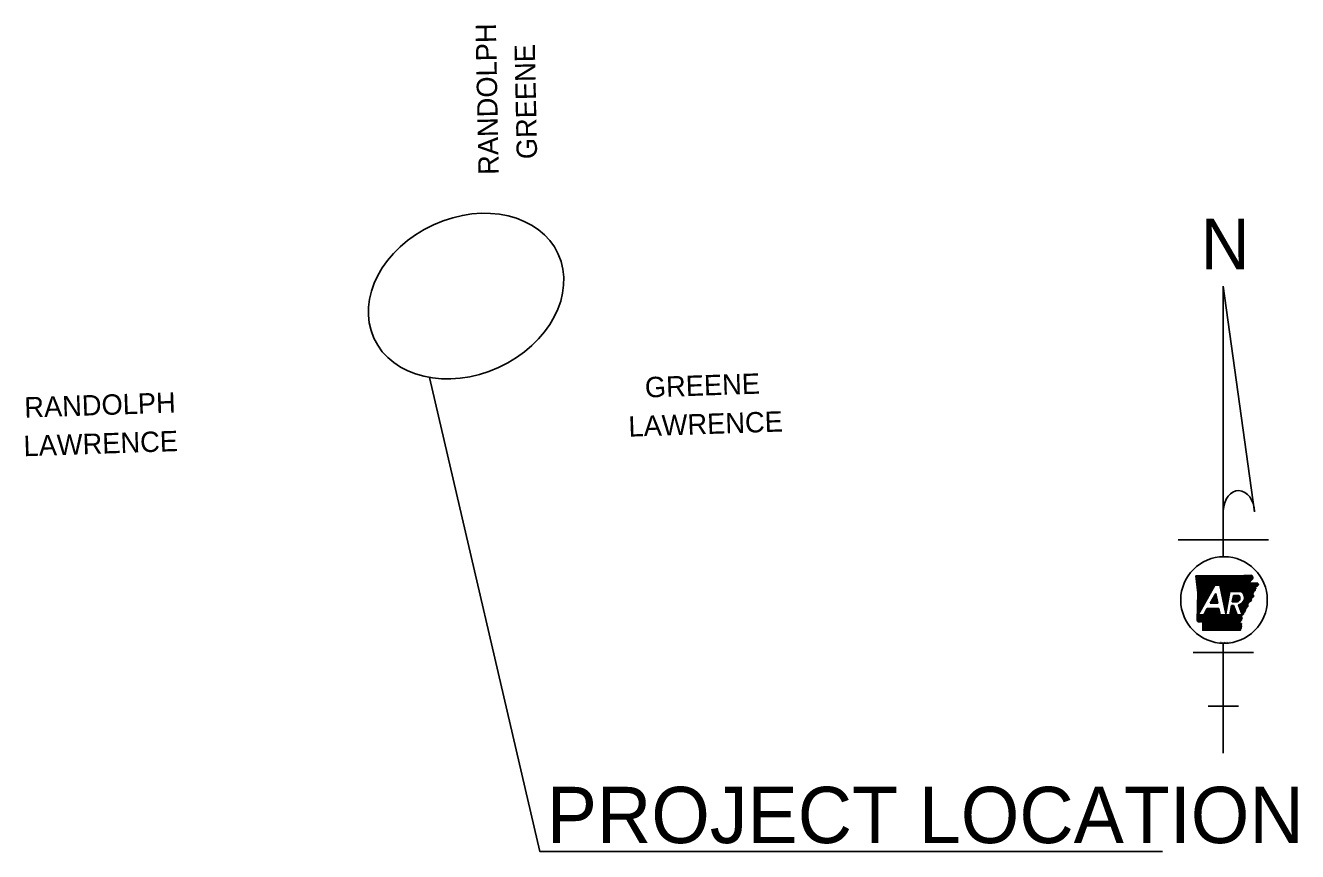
# Model space of a CAD drawing. Extents: x 166 to 3406, y 71 to 2074.
# Drawn here: x 345 to 1136, y 1409 to 1923 of the extents above; entities that cross this region are included whole.
import ezdxf

# ---------------------------------------------------------------- set-up
doc = ezdxf.new("R2010")
doc.units = 0
for name, color, linetype in [('2', 7, 'Continuous'), ('Default', 7, 'Continuous'), ('Level 30', 7, 'Continuous'), ('Level 6', 7, 'Continuous')]:
    doc.layers.add(name, color=color, linetype=linetype)

msp = doc.modelspace()

# ---------------------------------------------------------------- linework, layer by layer
at = {"layer": 'Default'}
msp.add_lwpolyline([(595.91, 1703.74), (664.57, 1409), (1051.65, 1409.03)], dxfattribs=at)
msp.add_ellipse((618.65, 1754.3), major_axis=(-57.31, -26.15), ratio=0.773836, dxfattribs=at)
at = {"layer": 'Level 6'}
for p, q in [((1089.53, 1760.46), (1108.93, 1620.22)), ((1089.53, 1592.29), (1089.53, 1760.46)), ((1061.44, 1602.69), (1117.61, 1602.69)), ((1072.49, 1580.24), (1072.72, 1580.47)), ((1072.57, 1579.58), (1073.47, 1580.47)), ((1072.66, 1578.92), (1074.21, 1580.47)), ((1072.74, 1578.26), (1074.95, 1580.47)), ((1072.82, 1577.6), (1075.7, 1580.47)), ((1072.9, 1576.94), (1076.44, 1580.47)), ((1072.99, 1576.28), (1077.18, 1580.47)), ((1073.07, 1575.62), (1077.92, 1580.47)), ((1073.15, 1574.95), (1078.67, 1580.47)), ((1073.23, 1574.29), (1079.41, 1580.47)), ((1073.32, 1573.63), (1080.15, 1580.47)), ((1073.4, 1572.97), (1080.9, 1580.47)), ((1073.48, 1572.31), (1081.64, 1580.47)), ((1073.56, 1571.65), (1082.38, 1580.47)), ((1073.59, 1564.24), (1089.83, 1580.48)), ((1073.61, 1565.01), (1089.08, 1580.48)), ((1073.64, 1565.78), (1088.34, 1580.48)), ((1073.65, 1570.99), (1083.13, 1580.47)), ((1073.66, 1566.55), (1087.6, 1580.48)), ((1073.69, 1567.32), (1086.85, 1580.48)), ((1073.72, 1568.08), (1086.11, 1580.47)), ((1073.73, 1570.33), (1083.87, 1580.47)), ((1073.74, 1568.85), (1085.36, 1580.47)), ((1073.77, 1569.62), (1084.62, 1580.47)), ((1073.81, 1556.22), (1084.18, 1574.54)), ((1084.18, 1574.54), (1087.26, 1574.54)), ((1084.63, 1574.54), (1090.57, 1580.48)), ((1085.37, 1574.54), (1091.32, 1580.49)), ((1086.11, 1574.54), (1092.07, 1580.49)), ((1086.86, 1574.54), (1092.82, 1580.5)), ((1087.32, 1574.26), (1093.58, 1580.52)), ((1087.45, 1573.64), (1094.33, 1580.53)), ((1087.58, 1573.03), (1095.09, 1580.54)), ((1087.71, 1572.42), (1095.84, 1580.55)), ((1087.84, 1571.81), (1096.6, 1580.56)), ((1087.97, 1571.19), (1097.35, 1580.57)), ((1088.11, 1570.58), (1098.11, 1580.59)), ((1088.24, 1569.97), (1098.86, 1580.6)), ((1088.37, 1569.36), (1099.62, 1580.61)), ((1088.5, 1568.74), (1100.38, 1580.62)), ((1088.63, 1568.13), (1101.13, 1580.63)), ((1088.76, 1567.52), (1101.89, 1580.64)), ((1088.89, 1566.91), (1102.64, 1580.66)), ((1089.02, 1566.3), (1103.4, 1580.68)), ((1094.19, 1570.72), (1104.16, 1580.69)), ((1094.93, 1570.72), (1104.93, 1580.71)), ((1095.67, 1570.72), (1105.69, 1580.73)), ((1096.42, 1570.72), (1106.45, 1580.75)), ((1097.16, 1570.72), (1107.21, 1580.76)), ((1097.9, 1570.72), (1107.37, 1580.19)), ((1098.65, 1570.72), (1107.73, 1579.8)), ((1099.39, 1570.72), (1107.83, 1579.16)), ((1100.13, 1570.72), (1106.13, 1576.72)), ((1100.81, 1570.65), (1105.99, 1575.83)), ((1101.21, 1570.31), (1106.77, 1575.87)), ((1101.58, 1569.93), (1107.55, 1575.91)), ((1101.9, 1569.51), (1108.34, 1575.95)), ((1102.17, 1569.04), (1109.12, 1575.99)), ((1102.4, 1568.52), (1109.9, 1576.03)), ((1102.57, 1567.95), (1110.61, 1575.99)), ((1102.67, 1567.31), (1110.96, 1575.59)), ((1110.63, 1574.52), (1111.3, 1575.2)), ((1073.46, 1560.4), (1079.71, 1566.65)), ((1073.49, 1561.17), (1080.68, 1568.36)), ((1073.51, 1561.93), (1081.65, 1570.07)), ((1073.54, 1562.7), (1082.62, 1571.79)), ((1073.56, 1563.47), (1083.59, 1573.5)), ((1081.44, 1563.41), (1084.83, 1569.4)), ((1081.47, 1563.41), (1085.29, 1567.23)), ((1082.22, 1563.41), (1085.42, 1566.62)), ((1082.36, 1565.04), (1085.16, 1567.84)), ((1083.33, 1566.76), (1085.03, 1568.46)), ((1084.3, 1568.47), (1084.9, 1569.07)), ((1089.15, 1565.68), (1093.37, 1569.9)), ((1089.28, 1565.07), (1093.21, 1569)), ((1089.42, 1564.46), (1093.06, 1568.1)), ((1089.55, 1563.85), (1092.9, 1567.2)), ((1089.68, 1563.23), (1092.74, 1566.3)), ((1093.51, 1570.72), (1100.71, 1570.72)), ((1095.08, 1564.22), (1098.99, 1568.13)), ((1095.23, 1565.12), (1098.25, 1568.13)), ((1095.39, 1566.02), (1097.5, 1568.13)), ((1095.55, 1566.92), (1096.76, 1568.13)), ((1095.7, 1567.82), (1096.02, 1568.13)), ((1095.76, 1568.13), (1099.14, 1568.13)), ((1095.82, 1564.22), (1099.4, 1567.8)), ((1096.57, 1564.22), (1099.66, 1567.31)), ((1097.31, 1564.22), (1099.79, 1566.7)), ((1099.45, 1561.12), (1107.69, 1569.36)), ((1099.65, 1560.57), (1107.83, 1568.75)), ((1099.85, 1560.03), (1107.97, 1568.15)), ((1100.05, 1559.49), (1108.11, 1567.54)), ((1101.88, 1564.28), (1107.55, 1569.96)), ((1102.52, 1565.67), (1109.27, 1572.42)), ((1102.68, 1566.57), (1109.18, 1573.08)), ((1108.44, 1570.84), (1109.35, 1571.76)), ((1073.36, 1557.32), (1075.83, 1559.79)), ((1073.38, 1558.09), (1076.8, 1561.51)), ((1073.41, 1558.86), (1077.77, 1563.22)), ((1073.43, 1559.63), (1078.74, 1564.93)), ((1073.49, 1552.25), (1081.31, 1560.07)), ((1073.94, 1551.95), (1082.05, 1560.07)), ((1074.47, 1551.74), (1082.79, 1560.07)), ((1075.35, 1551.88), (1083.54, 1560.07)), ((1076.11, 1551.89), (1084.28, 1560.07)), ((1076.69, 1551.73), (1085.02, 1560.07)), ((1076.71, 1551.01), (1085.77, 1560.07)), ((1076.72, 1550.27), (1086.51, 1560.07)), ((1076.72, 1549.53), (1086.9, 1559.71)), ((1076.72, 1548.79), (1087.03, 1559.1)), ((1076.72, 1548.05), (1087.16, 1558.49)), ((1079.54, 1560.07), (1077.37, 1556.22)), ((1078.21, 1557.71), (1080.56, 1560.07)), ((1079.18, 1559.43), (1079.82, 1560.07)), ((1086.83, 1560.07), (1079.54, 1560.07)), ((1081.44, 1563.41), (1086.11, 1563.41)), ((1082.96, 1563.41), (1085.55, 1566.01)), ((1083.7, 1563.41), (1085.69, 1565.39)), ((1084.16, 1546.56), (1096.94, 1559.35)), ((1084.45, 1563.41), (1085.82, 1564.78)), ((1084.9, 1546.56), (1097.14, 1558.81)), ((1085.19, 1563.41), (1085.95, 1564.17)), ((1085.93, 1563.41), (1086.08, 1563.56)), ((1089.81, 1562.62), (1092.59, 1565.4)), ((1089.94, 1562.01), (1092.43, 1564.5)), ((1090.07, 1561.4), (1092.27, 1563.6)), ((1090.2, 1560.78), (1092.12, 1562.7)), ((1090.33, 1560.17), (1091.96, 1561.8)), ((1090.46, 1559.56), (1091.8, 1560.9)), ((1090.59, 1558.95), (1091.65, 1560)), ((1090.73, 1558.34), (1091.49, 1559.1)), ((1093.81, 1556.96), (1096.74, 1559.89)), ((1093.97, 1557.86), (1096.54, 1560.43)), ((1094.13, 1558.76), (1096.34, 1560.98)), ((1094.28, 1559.66), (1096.14, 1561.52)), ((1094.44, 1560.56), (1095.92, 1562.05)), ((1094.6, 1561.46), (1095.18, 1562.05)), ((1095.95, 1562.05), (1094.7, 1562.05)), ((1095.08, 1564.22), (1098.16, 1564.22)), ((1098.1, 1556.22), (1095.95, 1562.05)), ((1098.05, 1564.22), (1099.73, 1565.9)), ((1098.99, 1562.36), (1101.26, 1556.22)), ((1099.05, 1562.2), (1099.28, 1562.43)), ((1099.25, 1561.66), (1100.67, 1563.07)), ((1100.26, 1558.94), (1104.71, 1563.4)), ((1100.46, 1558.4), (1104.63, 1562.58)), ((1100.66, 1557.86), (1104.55, 1561.75)), ((1100.86, 1557.32), (1103.14, 1559.6)), ((1101.06, 1556.77), (1102.82, 1558.53)), ((1105.57, 1564.26), (1106.61, 1565.3)), ((1073.22, 1552.72), (1076.72, 1556.22)), ((1073.23, 1553.48), (1075.98, 1556.22)), ((1073.26, 1554.25), (1075.23, 1556.22)), ((1073.28, 1555.01), (1074.49, 1556.22)), ((1073.31, 1555.78), (1073.89, 1556.36)), ((1073.33, 1556.55), (1074.86, 1558.08)), ((1077.37, 1556.22), (1073.81, 1556.22)), ((1076.72, 1547.31), (1087.29, 1557.88)), ((1076.74, 1546.58), (1087.43, 1557.26)), ((1077.48, 1546.57), (1087.56, 1556.65)), ((1078.22, 1546.57), (1087.87, 1556.22)), ((1078.96, 1546.57), (1088.61, 1556.22)), ((1079.7, 1546.57), (1089.36, 1556.22)), ((1080.45, 1546.57), (1090.1, 1556.22)), ((1081.19, 1546.57), (1090.84, 1556.22)), ((1081.93, 1546.57), (1091.59, 1556.22)), ((1082.67, 1546.57), (1092.33, 1556.22)), ((1083.42, 1546.57), (1093.07, 1556.22)), ((1085.64, 1546.56), (1097.34, 1558.26)), ((1086.38, 1546.56), (1097.54, 1557.72)), ((1087.13, 1546.56), (1097.74, 1557.18)), ((1093.68, 1556.22), (1087.65, 1556.22)), ((1087.87, 1546.56), (1097.95, 1556.63)), ((1088.61, 1546.56), (1098.28, 1556.22)), ((1089.35, 1546.56), (1099.02, 1556.22)), ((1090.09, 1546.55), (1099.76, 1556.22)), ((1090.84, 1546.55), (1100.51, 1556.22)), ((1090.86, 1557.72), (1091.33, 1558.2)), ((1090.99, 1557.11), (1091.18, 1557.3)), ((1091.58, 1546.55), (1100.76, 1555.73)), ((1092.32, 1546.55), (1100.79, 1555.02)), ((1093.06, 1546.55), (1100.82, 1554.31)), ((1093.81, 1546.55), (1100.86, 1553.6)), ((1094.55, 1546.55), (1099.63, 1551.63)), ((1095.29, 1546.55), (1099.86, 1551.12)), ((1096.03, 1546.54), (1100.09, 1550.61)), ((1101.26, 1556.22), (1098.1, 1556.22)), ((1096.77, 1546.54), (1100.32, 1550.09)), ((1097.52, 1546.54), (1100.55, 1549.58)), ((1098.26, 1546.54), (1100.74, 1549.03)), ((1099, 1546.54), (1100.41, 1547.95)), ((1099.74, 1546.54), (1100.07, 1546.87)), ((1089.53, 1470.24), (1089.53, 1538.49)), ((1070.81, 1532.69), (1108.25, 1532.69)), ((1080.17, 1499.44), (1098.89, 1499.44))]:
    msp.add_line(p, q, dxfattribs=at)
for points in [[(1072.46, 1580.47), (1082.72, 1580.47), (1091.72, 1580.49), (1102.34, 1580.65), (1107.26, 1580.77)], [(1072.46, 1580.47), (1082.72, 1580.47), (1091.72, 1580.49), (1102.33, 1580.65), (1107.26, 1580.77)], [(1073.6, 1564.53), (1073.78, 1569.93), (1072.46, 1580.47)], [(1073.21, 1552.73), (1073.78, 1569.93), (1072.46, 1580.47)], [(1087.26, 1574.54), (1091.07, 1556.71), (1093.51, 1570.72)], [(1110.48, 1576.05), (1111.37, 1575.13), (1109.15, 1573.31), (1109.39, 1571.47), (1107.49, 1570.22), (1108.14, 1567.4), (1106.68, 1566.06), (1106.55, 1564.61), (1104.77, 1563.97), (1104.5, 1561.24), (1103.22, 1559.87), (1102.6, 1557.81), (1100.74, 1556.1), (1100.88, 1553.1), (1099.61, 1551.68), (1100.77, 1549.1), (1099.97, 1546.54)], [(1105.73, 1575.82), (1110.55, 1576.06)], [(1105.73, 1575.81), (1110.55, 1576.06)], [(1084.83, 1569.4), (1086.11, 1563.41)], [(1095.08, 1564.22), (1095.76, 1568.13)], [(1073.21, 1552.73), (1073.6, 1564.53)], [(1087.65, 1556.22), (1086.83, 1560.07)], [(1094.7, 1562.05), (1093.68, 1556.22)], [(1099.97, 1546.54), (1076.73, 1546.58), (1076.71, 1551.71)], [(1099.97, 1546.53), (1076.73, 1546.58), (1076.72, 1551.71)]]:
    msp.add_lwpolyline(points, dxfattribs=at)
for centre, major_axis, ratio, start_param, end_param in [((1099.22, 1619.92), (-0.41, 13.48), 0.719778, 4.712385, 7.768526), ((1097.42, 1566.48), (-2.38, 0), 0.999987, 1.887169, 3.90762), ((1098.04, 1566.91), (-4.65, 0), 0.999987, 1.777838, 4.099264)]:
    msp.add_ellipse(centre, major_axis=major_axis, ratio=ratio, start_param=start_param, end_param=end_param, dxfattribs=at)
msp.add_ellipse((1089.97, 1565.39), major_axis=(26.9, 0), ratio=0.999976, dxfattribs=at)
for points in [[(1107.26, 1580.77), (1107.29, 1580.49), (1107.37, 1580.34), (1107.39, 1580.07), (1107.5, 1579.96), (1107.68, 1579.84), (1107.84, 1579.66), (1107.88, 1579.45), (1107.83, 1579.23), (1107.82, 1578.97), (1107.8, 1578.76), (1107.75, 1578.57), (1107.6, 1578.41), (1107.46, 1578.29), (1107.33, 1578.16), (1107.23, 1578.02), (1107.07, 1577.87), (1106.9, 1577.71), (1106.76, 1577.57), (1106.63, 1577.39), (1106.57, 1577.2), (1106.43, 1577.06), (1106.31, 1576.93), (1106.16, 1576.76), (1106.08, 1576.59), (1105.94, 1576.39), (1105.9, 1576.2), (1105.81, 1576.05), (1105.8, 1576.02)], [(1107.26, 1580.77), (1107.29, 1580.49), (1107.38, 1580.34), (1107.39, 1580.07), (1107.5, 1579.96), (1107.68, 1579.85), (1107.85, 1579.66), (1107.88, 1579.45), (1107.83, 1579.22), (1107.82, 1578.98), (1107.8, 1578.76), (1107.76, 1578.57), (1107.61, 1578.41), (1107.46, 1578.29), (1107.33, 1578.16), (1107.23, 1578.02), (1107.07, 1577.87), (1106.9, 1577.71), (1106.77, 1577.57), (1106.63, 1577.39), (1106.57, 1577.2), (1106.43, 1577.06), (1106.31, 1576.93), (1106.16, 1576.76), (1106.08, 1576.59), (1105.94, 1576.39), (1105.91, 1576.2), (1105.81, 1576.05), (1105.8, 1576.02)], [(1110.48, 1576.06), (1110.55, 1576.06), (1110.76, 1575.83), (1110.86, 1575.64), (1111, 1575.53), (1111.16, 1575.48), (1111.28, 1575.33), (1111.36, 1575.17), (1111.32, 1575.03), (1111.14, 1575.02), (1110.94, 1574.99), (1110.75, 1575), (1110.59, 1574.86), (1110.74, 1574.7), (1110.92, 1574.53), (1110.97, 1574.37), (1110.87, 1574.2), (1110.67, 1574.11), (1110.47, 1574.03), (1110.29, 1573.89), (1110.21, 1573.74), (1110.01, 1573.68), (1109.81, 1573.62), (1109.63, 1573.6), (1109.43, 1573.56), (1109.24, 1573.46), (1109.15, 1573.3), (1109.18, 1573.07), (1109.17, 1572.82), (1109.38, 1572.74), (1109.56, 1572.73), (1109.74, 1572.64), (1109.72, 1572.5), (1109.59, 1572.32), (1109.43, 1572.18), (1109.27, 1572.11), (1109.13, 1571.97), (1109.18, 1571.84), (1109.31, 1571.76), (1109.41, 1571.61), (1109.39, 1571.48), (1109.24, 1571.38), (1109.08, 1571.42), (1108.95, 1571.58), (1108.82, 1571.62), (1108.69, 1571.68), (1108.56, 1571.6), (1108.56, 1571.42), (1108.51, 1571.22), (1108.55, 1571.08), (1108.6, 1570.87), (1108.6, 1570.72), (1108.55, 1570.5), (1108.44, 1570.28), (1108.32, 1570.21), (1108.26, 1570.45), (1108.24, 1570.65), (1108.16, 1570.77), (1108.06, 1570.77), (1107.93, 1570.68), (1107.78, 1570.53), (1107.6, 1570.37), (1107.49, 1570.21), (1107.55, 1570.02), (1107.69, 1569.97), (1107.8, 1570), (1107.85, 1570.13), (1107.95, 1570.15), (1108.06, 1569.95)], [(1108.06, 1569.95), (1108.09, 1569.77), (1107.98, 1569.57), (1107.94, 1569.38), (1107.95, 1569.18), (1107.75, 1569.07), (1107.58, 1568.94), (1107.68, 1568.79), (1107.88, 1568.65), (1108.06, 1568.55), (1108.18, 1568.44), (1108.21, 1568.18), (1108.24, 1568.01), (1108.31, 1567.78), (1108.33, 1567.62), (1108.22, 1567.44), (1108.09, 1567.4), (1107.94, 1567.44), (1107.78, 1567.45), (1107.65, 1567.33), (1107.55, 1567.15), (1107.46, 1566.97), (1107.39, 1566.82), (1107.32, 1566.66), (1107.18, 1566.46), (1107.01, 1566.43), (1106.81, 1566.38), (1106.68, 1566.24), (1106.71, 1566.01), (1106.82, 1565.85), (1106.91, 1565.65), (1106.97, 1565.48), (1106.94, 1565.27), (1106.85, 1565.11), (1106.74, 1565.01), (1106.68, 1564.81), (1106.6, 1564.65), (1106.53, 1564.6), (1106.37, 1564.62), (1106.21, 1564.65), (1106.07, 1564.64), (1105.94, 1564.57), (1105.8, 1564.61), (1105.66, 1564.77), (1105.55, 1564.88), (1105.42, 1564.92), (1105.29, 1564.85), (1105.27, 1564.64), (1105.33, 1564.43), (1105.39, 1564.14), (1105.33, 1563.96), (1105.31, 1563.67)], [(1105.31, 1563.67), (1105.09, 1563.5), (1104.99, 1563.32), (1104.42, 1563.37), (1104.44, 1563.18), (1104.24, 1563.07), (1104.06, 1562.94), (1104.16, 1562.79), (1104.35, 1562.65), (1104.54, 1562.54), (1104.66, 1562.44), (1104.69, 1562.17), (1104.73, 1562.01), (1104.79, 1561.78), (1104.81, 1561.62), (1104.7, 1561.44), (1104.57, 1561.4), (1104.43, 1561.44), (1104.26, 1561.45), (1104.13, 1561.33), (1104.04, 1561.15), (1103.94, 1560.97), (1103.87, 1560.82), (1103.8, 1560.65), (1103.66, 1560.46), (1103.49, 1560.43), (1103.29, 1560.38), (1103.17, 1560.24), (1103.19, 1560.01), (1103.3, 1559.85), (1103.39, 1559.65), (1103.45, 1559.48), (1103.42, 1559.27), (1103.34, 1559.1), (1103.22, 1559.01), (1103.17, 1558.81), (1103.08, 1558.65), (1103.01, 1558.61), (1102.86, 1558.62), (1102.69, 1558.65), (1102.55, 1558.64), (1102.42, 1558.57), (1102.29, 1558.61), (1102.15, 1558.76), (1102.03, 1558.88), (1101.9, 1558.92), (1101.77, 1558.85), (1101.75, 1558.64), (1101.81, 1558.43), (1101.87, 1558.13), (1101.81, 1557.96), (1101.79, 1557.66)], [(1076.72, 1551.71), (1076.74, 1551.69), (1076.62, 1551.78), (1076.45, 1551.86), (1076.27, 1551.87), (1076.03, 1551.9), (1075.84, 1551.92), (1075.64, 1552.06), (1075.42, 1551.92), (1075.18, 1551.81), (1075.04, 1551.93), (1074.86, 1551.85), (1074.73, 1551.89), (1074.51, 1551.74), (1074.29, 1551.8), (1074.15, 1551.75), (1073.96, 1551.76), (1073.92, 1551.97), (1073.73, 1552), (1073.57, 1552.09), (1073.47, 1552.31), (1073.39, 1552.49), (1073.21, 1552.73)], [(1076.71, 1551.71), (1076.74, 1551.69), (1076.62, 1551.78), (1076.45, 1551.86), (1076.27, 1551.87), (1076.03, 1551.9), (1075.84, 1551.92), (1075.63, 1552.06), (1075.42, 1551.92), (1075.18, 1551.81), (1075.04, 1551.93), (1074.85, 1551.85), (1074.73, 1551.89), (1074.51, 1551.74), (1074.3, 1551.8), (1074.14, 1551.75), (1073.95, 1551.76), (1073.92, 1551.97), (1073.73, 1552), (1073.57, 1552.09), (1073.47, 1552.32), (1073.39, 1552.49), (1073.21, 1552.73)], [(1100.94, 1555.28), (1100.88, 1555.13), (1100.8, 1554.88), (1100.83, 1554.66), (1100.92, 1554.48), (1101.07, 1554.38), (1101.24, 1554.23), (1101.23, 1554.01), (1101.13, 1553.93), (1100.9, 1553.98), (1100.73, 1554.06), (1100.59, 1554.02), (1100.4, 1553.92), (1100.25, 1553.9), (1100.25, 1553.59), (1100.45, 1553.38), (1100.62, 1553.38), (1100.82, 1553.36), (1100.89, 1553.13), (1100.77, 1552.93), (1100.59, 1552.84), (1100.34, 1552.96), (1100.17, 1553.08), (1100, 1553.19), (1099.79, 1553.25), (1099.66, 1553.22), (1099.61, 1552.96), (1099.71, 1552.72), (1099.87, 1552.55), (1100.02, 1552.34), (1100, 1552.17), (1099.89, 1552.13), (1099.68, 1552.09), (1099.56, 1552.03), (1099.53, 1551.97), (1099.6, 1551.76), (1099.65, 1551.52), (1099.65, 1551.34), (1099.58, 1551.18), (1099.47, 1550.93), (1099.49, 1550.77), (1099.56, 1550.69), (1099.66, 1550.71), (1099.79, 1550.8), (1099.87, 1550.9), (1099.94, 1551.03), (1100.07, 1551.14), (1100.23, 1551.04), (1100.27, 1550.84), (1100.18, 1550.67), (1100.04, 1550.59), (1099.88, 1550.53), (1099.76, 1550.39), (1099.79, 1550.23), (1099.89, 1550.14), (1100.12, 1550.19), (1100.28, 1550.26), (1100.37, 1550.34), (1100.48, 1550.45), (1100.53, 1550.56), (1100.62, 1550.67), (1100.76, 1550.71), (1100.83, 1550.61), (1100.8, 1550.39), (1100.72, 1550.19), (1100.59, 1550.02), (1100.46, 1549.9), (1100.3, 1549.64), (1100.33, 1549.4), (1100.4, 1549.2), (1100.48, 1549.05), (1100.63, 1549.08), (1100.8, 1549.1), (1100.9, 1549.02), (1100.9, 1548.84), (1100.77, 1548.66), (1100.65, 1548.5), (1100.59, 1548.28), (1100.61, 1548.11), (1100.61, 1547.97), (1100.56, 1547.81), (1100.47, 1547.72), (1100.23, 1547.73), (1099.99, 1547.75), (1099.86, 1547.68), (1099.88, 1547.46), (1100.02, 1547.3), (1100.13, 1547.22), (1100.27, 1547.04), (1100.34, 1546.9), (1100.32, 1546.77), (1100.23, 1546.66), (1099.97, 1546.53)], [(1100.94, 1555.28), (1100.88, 1555.13), (1100.8, 1554.88), (1100.83, 1554.66), (1100.92, 1554.48), (1101.07, 1554.38), (1101.24, 1554.23), (1101.23, 1554.01), (1101.13, 1553.93), (1100.9, 1553.98), (1100.73, 1554.06), (1100.59, 1554.02), (1100.4, 1553.92), (1100.25, 1553.9), (1100.25, 1553.59), (1100.45, 1553.38), (1100.62, 1553.38), (1100.82, 1553.36), (1100.89, 1553.13), (1100.77, 1552.93), (1100.59, 1552.84), (1100.34, 1552.96), (1100.17, 1553.08), (1100, 1553.19), (1099.79, 1553.25), (1099.66, 1553.22), (1099.61, 1552.96), (1099.71, 1552.72), (1099.87, 1552.55), (1100.02, 1552.34), (1100, 1552.17), (1099.89, 1552.13), (1099.68, 1552.09), (1099.56, 1552.03), (1099.53, 1551.97), (1099.6, 1551.76), (1099.65, 1551.52), (1099.65, 1551.34), (1099.58, 1551.18), (1099.47, 1550.93), (1099.49, 1550.77), (1099.56, 1550.69), (1099.66, 1550.71), (1099.79, 1550.8), (1099.87, 1550.9), (1099.94, 1551.03), (1100.07, 1551.14), (1100.23, 1551.04), (1100.27, 1550.84), (1100.18, 1550.67), (1100.04, 1550.59), (1099.88, 1550.53), (1099.76, 1550.39), (1099.79, 1550.23), (1099.89, 1550.14), (1100.12, 1550.19), (1100.28, 1550.26), (1100.37, 1550.34), (1100.48, 1550.45), (1100.53, 1550.56), (1100.62, 1550.67), (1100.76, 1550.71), (1100.83, 1550.61), (1100.8, 1550.39), (1100.72, 1550.19), (1100.59, 1550.02), (1100.46, 1549.9), (1100.3, 1549.64), (1100.33, 1549.4), (1100.4, 1549.2), (1100.48, 1549.05), (1100.63, 1549.08), (1100.8, 1549.1), (1100.9, 1549.02), (1100.9, 1548.84), (1100.77, 1548.66), (1100.65, 1548.5), (1100.59, 1548.28), (1100.61, 1548.11), (1100.61, 1547.97), (1100.56, 1547.81), (1100.47, 1547.72), (1100.23, 1547.73), (1099.99, 1547.75), (1099.86, 1547.68), (1099.88, 1547.46), (1100.02, 1547.3), (1100.13, 1547.22), (1100.27, 1547.04), (1100.34, 1546.9), (1100.32, 1546.77), (1100.23, 1546.66), (1099.97, 1546.53)], [(1101.79, 1557.66), (1101.78, 1557.66), (1101.66, 1557.51), (1101.73, 1557.29), (1101.97, 1557.2), (1102.09, 1556.99), (1102.09, 1556.8), (1102.01, 1556.53), (1101.9, 1556.41), (1101.68, 1556.36), (1101.51, 1556.33), (1101.48, 1556.04), (1101.4, 1555.89), (1101.27, 1555.85), (1101.08, 1555.94), (1100.96, 1555.99), (1100.83, 1556.05), (1100.65, 1556.16), (1100.51, 1556.14), (1100.55, 1555.86), (1100.56, 1555.85), (1100.72, 1555.64), (1100.87, 1555.47), (1100.94, 1555.28)], [(1101.79, 1557.66), (1101.78, 1557.66), (1101.66, 1557.51), (1101.73, 1557.29), (1101.97, 1557.2), (1102.09, 1556.99), (1102.09, 1556.8), (1102.01, 1556.53), (1101.9, 1556.41), (1101.68, 1556.36), (1101.51, 1556.33), (1101.48, 1556.04), (1101.4, 1555.89), (1101.27, 1555.85), (1101.08, 1555.94), (1100.96, 1555.99), (1100.83, 1556.05), (1100.65, 1556.16), (1100.51, 1556.14), (1100.55, 1555.86), (1100.56, 1555.85), (1100.72, 1555.64), (1100.87, 1555.47), (1100.94, 1555.28)]]:
    msp.add_spline(points, degree=3, dxfattribs=at)

# ---------------------------------------------------------------- texts
at = {"layer": '2'}
msp.add_text('PROJECT LOCATION', height=35, dxfattribs=at).set_placement((668.82, 1414.24))
at = {"layer": 'Level 30'}
for s, rotation, p in [('RANDOLPH', 91.13842, (639.05, 1829.79)), ('GREENE', 91.13842, (662.86, 1839.56)), ('GREENE', 1.93545, (730.07, 1691.25)), ('RANDOLPH', 1.93545, (344.19, 1678.73)), ('LAWRENCE', 1.93545, (719.84, 1666.9)), ('LAWRENCE', 1.93545, (343.72, 1654.72))]:
    msp.add_text(s, height=12.672, rotation=rotation, dxfattribs=at).set_placement(p)
at = {"layer": 'Level 6'}
for s, height, p in [('N', 31.3, (1075.58, 1771.04)), ('STS 10-03-17', 0.7778, (1087.39, 1538.71))]:
    msp.add_text(s, height=height, dxfattribs=at).set_placement(p)

doc.saveas('drawing.dxf')
